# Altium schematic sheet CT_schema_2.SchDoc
size 276 x 169 mm
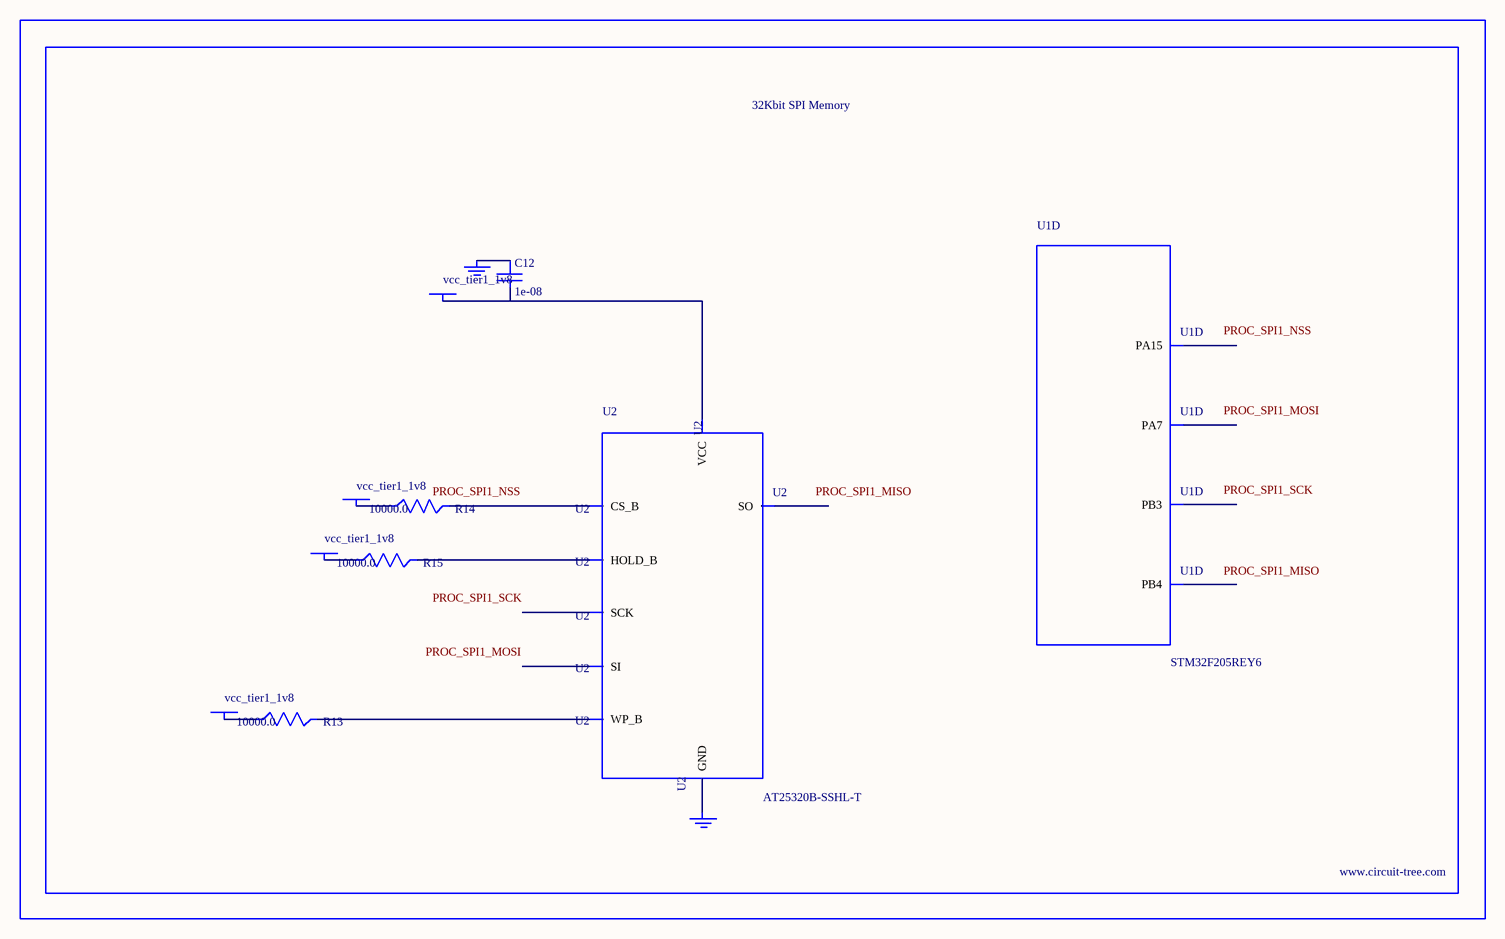
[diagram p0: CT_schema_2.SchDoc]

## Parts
BORDER1  (no value)
C12  1e-08  [C0402]
GND_INSTANCE_1_0  (no value)
GND_INSTANCE_1_1  (no value)
POWER_INSTANCE_1_0  vcc_tier1_1v8
POWER_INSTANCE_1_1  vcc_tier1_1v8
POWER_INSTANCE_1_2  vcc_tier1_1v8
POWER_INSTANCE_1_3  vcc_tier1_1v8
R13  10000.0  [R0603]
R14  10000.0  [R0603]
R15  10000.0  [R0603]
U1  STM32F205REY6  [WLCSP66]  (part D of 7)
U2  AT25320B-SSHL-T  [SOIC-8]

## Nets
NetC12_1: C12.1 GND_INSTANCE_1_0.0(GND)
NetC12_2: C12.2 POWER_INSTANCE_1_3.0(PWR) U2.8(VCC)
NetGND_INSTANCE_1_1_0: GND_INSTANCE_1_1.0(GND) U2.4(GND)
NetPOWER_INSTANCE_1_0_0: POWER_INSTANCE_1_0.0(PWR) R14.1
NetPOWER_INSTANCE_1_1_0: POWER_INSTANCE_1_1.0(PWR) R13.1
NetPOWER_INSTANCE_1_2_0: POWER_INSTANCE_1_2.0(PWR) R15.1
NetR13_2: R13.2 U2.3(WP_B)
NetR14_2: R14.2 U2.1(CS_B)
NetR15_2: R15.2 U2.7(HOLD_B)

Not connected (* = marked no-connect by the designer): U1 A2(PA15) A4(PB3) B4(PB4) J7(PA7); U2 2(SO) 5(SI) 6(SCK)

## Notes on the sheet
- Labels drawn without touching a wire or pin: PROC_SPI1_MISO, PROC_SPI1_MOSI, PROC_SPI1_NSS, PROC_SPI1_SCK

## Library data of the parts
BORDER1 = BORDER_PAGE1
C12 = C0402C103K3RAC
GND_INSTANCE_1_0 GND_INSTANCE_1_1 = GND
POWER_INSTANCE_1_0-POWER_INSTANCE_1_3 = PWR
R13-R15 = RC0603JR-0710KL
